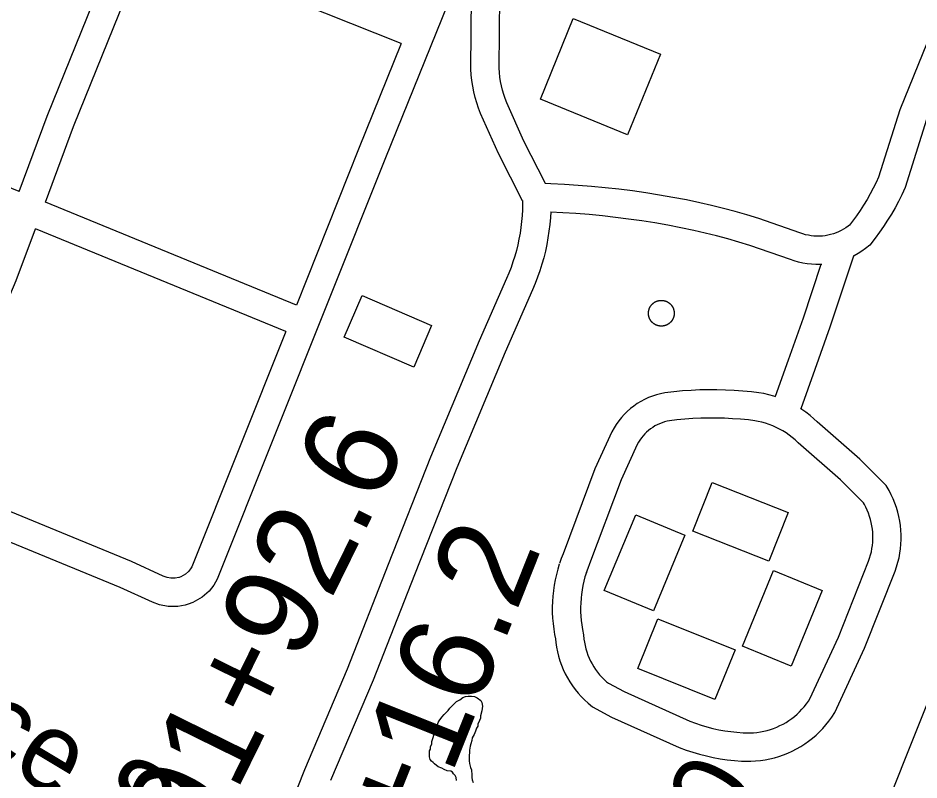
# Model space of a CAD drawing. Extents: x 3677843 to 3715951, y 511991 to 537744.
# Drawn here: x 3699179 to 3700134, y 530096 to 530904 of the extents above; entities that cross this region are included whole.
import ezdxf

# ---------------------------------------------------------------- set-up
doc = ezdxf.new("R2010")
doc.units = 0
for name, color, linetype in [('V-BLDG-IDEN', 7, 'Continuous'), ('V-BLDG-OTLN', 7, 'Continuous'), ('V-RIVR-RANG-IDEN', 7, 'Continuous'), ('V-ROAD-CNTR', 7, 'Continuous'), ('V-SITE-STRC', 7, 'Continuous'), ('V-SITE-VEGE', 7, 'Continuous'), ('V-SURV-IDEN', 7, 'Continuous'), ('V-TOPO-BNDY', 7, 'Continuous')]:
    doc.layers.add(name, color=color, linetype=linetype)

msp = doc.modelspace()

# ---------------------------------------------------------------- linework, layer by layer
at = {"layer": 'V-BLDG-OTLN'}
for points in [[(3699732.81, 530817.61), (3699767.66, 530903.08), (3699860.1, 530865.38), (3699825.24, 530779.93)], [(3699543.77, 530609.69), (3699617.52, 530578.01), (3699598.59, 530533.94), (3699524.84, 530565.62)], [(3699974.84, 530328.15), (3699894.45, 530360.14), (3699914.94, 530411.63), (3699995.33, 530379.63)], [(3699885.9, 530355.71), (3699852.63, 530275.63), (3699800.5, 530297.29), (3699833.77, 530377.36)], [(3700031.5, 530297.11), (3699998.55, 530217.03), (3699946.89, 530238.28), (3699979.83, 530318.36)], [(3699917.82, 530181.6), (3699836.15, 530214.54), (3699857.41, 530267.22), (3699939.07, 530234.27)]]:
    msp.add_lwpolyline(points, close=True, dxfattribs=at)
at = {"layer": 'V-ROAD-CNTR'}
for points in [[(3699695.42, 531069.1), (3699568.01, 530753.72), (3699390.39, 530309.01), (3699386.76, 530302.86), (3699381.67, 530296.5), (3699374.27, 530289.96), (3699364.58, 530284.44), (3699359.58, 530282.57), (3699356.41, 530281.64), (3699348.49, 530280.21), (3699338.36, 530280.19), (3699329.17, 530281.92), (3699321.57, 530284.76), (3699287.45, 530300.47), (3699085.23, 530383.37), (3699069.85, 530390.63), (3699063.87, 530399.71), (3699062.2, 530405.56), (3699060.55, 530414.61), (3699063.09, 530432.38), (3699070.46, 530451.51), (3699149.4, 530636.86), (3699169.9, 530691.83)], [(3699180.39, 530719.95), (3699210.17, 530799.78), (3699288.77, 530994.73)], [(3699208.17, 530708.58), (3699238.14, 530788.93), (3699316.64, 530983.63)], [(3699585.29, 530876.59), (3699316.64, 530983.63)], [(3700171.65, 530949.68), (3700113.85, 530806.5), (3700091.28, 530734.98), (3700088.71, 530729.46), (3700085.64, 530723.33), (3700082.39, 530717.3), (3700078.98, 530711.36), (3700075.4, 530705.51), (3700071.65, 530699.77), (3700067.74, 530694.14), (3700063.67, 530688.63), (3700060.35, 530684.39), (3700059.03, 530683.31), (3700056.61, 530681.57), (3700054.1, 530679.97), (3700051.5, 530678.51), (3700048.83, 530677.2), (3700046.08, 530676.04), (3700043.27, 530675.04), (3700040.42, 530674.21), (3700037.52, 530673.53), (3700034.58, 530673.02), (3700031.61, 530672.68), (3700028.64, 530672.51), (3700025.66, 530672.5), (3700022.69, 530672.67), (3700019.73, 530673), (3700016.79, 530673.5), (3700013.88, 530674.17), (3700011.02, 530675), (3700007.79, 530676.13), (3699964.22, 530691.33), (3699951.7, 530695.13), (3699939.29, 530698.65), (3699926.82, 530701.97), (3699914.3, 530705.07), (3699901.7, 530707.96), (3699887.47, 530710.93), (3699873.24, 530713.65), (3699858.97, 530716.16), (3699844.66, 530718.44), (3699830.31, 530720.49), (3699815.94, 530722.32), (3699801.54, 530723.92), (3699787.11, 530725.3), (3699772.66, 530726.45), (3699758.2, 530727.37), (3699743.72, 530728.07), (3699737.73, 530728.26)], [(3699713.9, 530709.9), (3699688.24, 530760.35), (3699669.38, 530802.45), (3699667.18, 530808.16), (3699665.27, 530813.89), (3699663.6, 530819.7), (3699662.2, 530825.58), (3699661.06, 530831.51), (3699660.18, 530837.5), (3699659.56, 530843.51), (3699659.21, 530849.69), (3699659.71, 530927.96)], [(3699738.22, 530728.25), (3699715.31, 530773.29), (3699697.09, 530813.98), (3699695.42, 530818.31), (3699693.93, 530822.78), (3699692.63, 530827.32), (3699691.53, 530831.9), (3699690.64, 530836.53), (3699689.95, 530841.2), (3699689.48, 530845.89), (3699689.21, 530850.45), (3699689.71, 530927.25)], [(3699585.29, 530876.59), (3699540.17, 530764.9), (3699474.16, 530599.62)], [(3699180.39, 530719.95), (3698900.65, 530834.54)], [(3700142.11, 530796.35), (3700119.3, 530724.08), (3700115.72, 530716.41), (3700112.27, 530709.51), (3700108.62, 530702.72), (3700104.78, 530696.04), (3700100.75, 530689.47), (3700096.53, 530683.01), (3700092.13, 530676.68), (3700087.56, 530670.47), (3700081.89, 530663.24), (3700077.28, 530659.49), (3700073.48, 530656.75), (3700069.53, 530654.23), (3700065.45, 530651.93), (3700064.39, 530651.41)], [(3699474.16, 530599.62), (3699208.17, 530708.58)], [(3699713.9, 530710.36), (3699713.92, 530706.93), (3699713.77, 530700.66), (3699713.43, 530694.41), (3699712.89, 530688.16), (3699712.16, 530681.93), (3699711.23, 530675.73), (3699710.12, 530669.56), (3699708.81, 530663.43), (3699707.31, 530657.34), (3699705.62, 530651.3), (3699703.75, 530645.32), (3699701.69, 530639.39), (3699699.45, 530633.54), (3699696.99, 530627.66), (3699667.95, 530561.55), (3699616.43, 530438.58), (3699571.63, 530324.75), (3699527.9, 530213.65), (3699482.69, 530107.12), (3699459.1, 530047.48)], [(3699743.69, 530698.3), (3699743.36, 530692.3), (3699742.74, 530685.12), (3699741.9, 530677.97), (3699740.84, 530670.84), (3699739.55, 530663.76), (3699738.05, 530656.72), (3699736.33, 530649.72), (3699734.39, 530642.78), (3699732.24, 530635.91), (3699729.87, 530629.1), (3699727.3, 530622.38), (3699724.56, 530615.83), (3699695.52, 530549.72), (3699644.22, 530427.29), (3699599.54, 530313.77), (3699555.67, 530202.29), (3699510.45, 530095.75)], [(3700031.03, 530642.6), (3700029.54, 530642.51), (3700024.86, 530642.5), (3700020.18, 530642.76), (3700015.53, 530643.28), (3700010.91, 530644.07), (3700006.36, 530645.11), (3700001.86, 530646.41), (3699997.86, 530647.82), (3699954.93, 530662.8), (3699943.25, 530666.34), (3699931.33, 530669.73), (3699919.36, 530672.91), (3699907.34, 530675.89), (3699895.29, 530678.66), (3699881.6, 530681.51), (3699867.83, 530684.14), (3699854.02, 530686.57), (3699840.17, 530688.77), (3699826.29, 530690.76), (3699812.38, 530692.53), (3699798.45, 530694.08), (3699784.49, 530695.42), (3699770.52, 530696.53), (3699756.52, 530697.42), (3699743.43, 530698.05)], [(3699463.03, 530571.76), (3699363.39, 530322.28), (3699362.01, 530319.95), (3699359.87, 530317.27), (3699356.72, 530314.49), (3699351.81, 530311.69), (3699350.11, 530311.06), (3699349.52, 530310.88), (3699345.77, 530310.2), (3699341.13, 530310.2), (3699337.25, 530310.92), (3699333.12, 530312.47), (3699299.42, 530327.99), (3699097.33, 530410.84), (3699090.28, 530414.16), (3699091.45, 530412.37), (3699091.45, 530412.4), (3699090.94, 530415.2), (3699092.3, 530424.76), (3699098.26, 530440.24), (3699177.27, 530625.73), (3699197.68, 530680.45)], [(3699463.03, 530571.76), (3699197.68, 530680.45)], [(3700064.74, 530651.58), (3700039.71, 530576.02), (3700023.62, 530531.23), (3700008.77, 530489.74)], [(3700030.14, 530642.54), (3700011.35, 530585.81), (3699995.38, 530541.35), (3699981.53, 530502.66)], [(3699982.21, 530502.44), (3699980.3, 530503.07), (3699975.05, 530504.55), (3699969.73, 530505.77), (3699964.27, 530506.74), (3699956.42, 530507.66), (3699947.32, 530508.51), (3699938.21, 530509.15), (3699929.09, 530509.58), (3699919.95, 530509.8), (3699910.81, 530509.81), (3699901.67, 530509.61), (3699892.54, 530509.2), (3699883.42, 530508.57), (3699874.32, 530507.74), (3699864.77, 530506.64), (3699860.16, 530505.71), (3699855.82, 530504.56), (3699851.55, 530503.16), (3699847.36, 530501.51), (3699843.28, 530499.63), (3699839.32, 530497.52), (3699835.49, 530495.18), (3699831.79, 530492.62), (3699828.26, 530489.85), (3699824.88, 530486.88), (3699821.68, 530483.72), (3699818.68, 530480.39), (3699815.87, 530476.89), (3699813.26, 530473.22), (3699810.88, 530469.41), (3699808.66, 530465.37), (3699790.66, 530426), (3699756.82, 530336), (3699754.84, 530330.94), (3699753.01, 530325.7)], [(3699746.52, 530296.73), (3699745.94, 530291.21), (3699745.55, 530285.4), (3699745.38, 530279.57), (3699745.43, 530273.74), (3699745.71, 530267.91), (3699746.21, 530262.1), (3699746.94, 530256.31), (3699747.88, 530250.56), (3699748.83, 530245.9), (3699749.2, 530242.11), (3699749.91, 530237.2), (3699750.87, 530232.34), (3699752.06, 530227.52), (3699753.49, 530222.77), (3699755.14, 530218.1), (3699757.03, 530213.5), (3699759.14, 530209.02), (3699761.46, 530204.64), (3699764, 530200.37), (3699766.74, 530196.24), (3699769.68, 530192.24), (3699772.81, 530188.4), (3699776.13, 530184.71), (3699779.63, 530181.19), (3699783.29, 530177.84), (3699787.96, 530173.97), (3699808.24, 530163.05), (3699879.84, 530130.82), (3699887.13, 530128.13), (3699894.26, 530125.79), (3699901.46, 530123.69), (3699908.73, 530121.84), (3699916.07, 530120.24), (3699923.45, 530118.91), (3699930.88, 530117.82), (3699938.34, 530117), (3699945.8, 530116.44), (3699950.74, 530116.23), (3699955.8, 530116.25), (3699960.86, 530116.5), (3699965.91, 530117), (3699970.91, 530117.73), (3699975.88, 530118.69), (3699980.81, 530119.89), (3699985.67, 530121.32), (3699990.46, 530122.98), (3699995.16, 530124.86), (3699999.77, 530126.96), (3700004.28, 530129.27), (3700008.67, 530131.8), (3700012.94, 530134.52), (3700017.08, 530137.45), (3700021.07, 530140.57), (3700024.91, 530143.87), (3700028.59, 530147.35), (3700032.11, 530151), (3700035.45, 530154.81), (3700038.6, 530158.77), (3700041.56, 530162.88), (3700044.74, 530167.74), (3700076.2, 530235.95), (3700108.75, 530317.71), (3700110.35, 530322.33), (3700111.72, 530327.03), (3700112.88, 530331.79), (3700113.8, 530336.61), (3700114.49, 530341.46), (3700114.94, 530346.34), (3700115.16, 530351.24), (3700115.15, 530356.14), (3700114.9, 530361.03), (3700114.42, 530365.91), (3700113.7, 530370.75), (3700112.75, 530375.57), (3700111.57, 530380.33), (3700110.17, 530385.02), (3700108.54, 530389.64), (3700106.69, 530394.18), (3700104.63, 530398.63), (3700102.35, 530402.96), (3700099.09, 530408.53), (3700071.3, 530436.34), (3700026.19, 530475.78), (3700022.69, 530479.08), (3700018.55, 530482.63), (3700014.24, 530485.97), (3700009.78, 530489.1), (3700008.62, 530489.83)], [(3699776.35, 530293.58), (3699775.83, 530288.63), (3699775.52, 530283.96), (3699775.38, 530279.28), (3699775.42, 530274.6), (3699775.65, 530269.92), (3699776.05, 530265.26), (3699776.63, 530260.61), (3699777.39, 530255.99), (3699778.54, 530250.34), (3699778.99, 530245.72), (3699779.49, 530242.27), (3699780.17, 530238.83), (3699781, 530235.45), (3699782.01, 530232.11), (3699783.17, 530228.81), (3699784.5, 530225.59), (3699785.99, 530222.42), (3699787.62, 530219.34), (3699789.4, 530216.34), (3699791.33, 530213.43), (3699793.4, 530210.62), (3699795.61, 530207.91), (3699797.94, 530205.32), (3699800.4, 530202.84), (3699802.98, 530200.48), (3699804.81, 530198.97), (3699821.52, 530189.97), (3699891.2, 530158.61), (3699897.02, 530156.46), (3699903.15, 530154.44), (3699909.36, 530152.63), (3699915.62, 530151.04), (3699921.93, 530149.67), (3699928.29, 530148.52), (3699934.68, 530147.59), (3699941.1, 530146.88), (3699947.57, 530146.4), (3699951.34, 530146.23), (3699955, 530146.24), (3699958.64, 530146.43), (3699962.27, 530146.78), (3699965.89, 530147.31), (3699969.48, 530148.01), (3699973.02, 530148.87), (3699976.53, 530149.9), (3699979.98, 530151.1), (3699983.37, 530152.45), (3699986.7, 530153.96), (3699989.95, 530155.63), (3699993.11, 530157.45), (3699996.19, 530159.42), (3699999.17, 530161.53), (3700002.05, 530163.78), (3700004.82, 530166.16), (3700007.48, 530168.67), (3700010.01, 530171.3), (3700012.41, 530174.04), (3700014.69, 530176.9), (3700016.82, 530179.86), (3700018.41, 530182.3), (3700048.63, 530247.79), (3700080.62, 530328.18), (3700081.76, 530331.46), (3700082.73, 530334.78), (3700083.55, 530338.15), (3700084.2, 530341.54), (3700084.68, 530344.97), (3700085.01, 530348.42), (3700085.16, 530351.88), (3700085.15, 530355.34), (3700084.98, 530358.79), (3700084.64, 530362.24), (3700084.13, 530365.66), (3700083.46, 530369.05), (3700082.63, 530372.41), (3700081.63, 530375.73), (3700080.49, 530378.99), (3700079.18, 530382.2), (3700077.72, 530385.33), (3700076.12, 530388.4), (3700075.15, 530390.04), (3700050.79, 530414.42), (3700006.01, 530453.57), (3700002.63, 530456.76), (3699999.59, 530459.37), (3699996.42, 530461.83), (3699993.14, 530464.13), (3699989.76, 530466.27), (3699986.27, 530468.24), (3699982.69, 530470.04), (3699979.03, 530471.67), (3699975.29, 530473.12), (3699971.49, 530474.39), (3699967.64, 530475.47), (3699963.74, 530476.36), (3699959.89, 530477.05), (3699953.28, 530477.82), (3699944.87, 530478.61), (3699936.45, 530479.2), (3699928.01, 530479.6), (3699919.57, 530479.81), (3699911.13, 530479.81), (3699902.68, 530479.63), (3699894.24, 530479.24), (3699885.81, 530478.67), (3699877.4, 530477.9), (3699869.49, 530476.99), (3699867, 530476.48), (3699864.33, 530475.78), (3699861.71, 530474.92), (3699859.14, 530473.91), (3699856.64, 530472.76), (3699854.21, 530471.46), (3699851.86, 530470.02), (3699849.59, 530468.45), (3699847.42, 530466.75), (3699845.35, 530464.93), (3699843.39, 530463), (3699841.54, 530460.94), (3699839.82, 530458.8), (3699838.22, 530456.55), (3699836.76, 530454.21), (3699835.49, 530451.9), (3699818.38, 530414.47), (3699784.83, 530325.25), (3699782.97, 530320.52), (3699781.34, 530315.83)], [(3699752.83, 530325.15), (3699751.21, 530319.85), (3699749.72, 530314.22), (3699748.44, 530308.53), (3699747.39, 530302.79), (3699746.59, 530297.31)], [(3699781.52, 530316.38), (3699780.06, 530311.62), (3699778.87, 530307.1), (3699777.84, 530302.53), (3699776.99, 530297.92), (3699776.28, 530293)]]:
    msp.add_lwpolyline(points, dxfattribs=at)
at = {"layer": 'V-SITE-STRC'}
for points in [[(3699848.12, 530595.59), (3699848.21, 530595.81), (3699848.29, 530596.03), (3699848.39, 530596.25), (3699848.48, 530596.47), (3699848.58, 530596.69), (3699848.68, 530596.9), (3699848.79, 530597.12), (3699848.9, 530597.33), (3699849.01, 530597.54), (3699849.12, 530597.74), (3699849.25, 530597.95), (3699849.37, 530598.15), (3699849.5, 530598.35), (3699849.63, 530598.55), (3699849.77, 530598.75), (3699849.9, 530598.94), (3699850.04, 530599.13), (3699850.19, 530599.32), (3699850.34, 530599.51), (3699850.49, 530599.7), (3699850.65, 530599.88), (3699850.8, 530600.05), (3699850.96, 530600.23), (3699851.13, 530600.4), (3699851.29, 530600.57), (3699851.46, 530600.74), (3699851.64, 530600.9), (3699851.81, 530601.07), (3699851.99, 530601.22), (3699852.17, 530601.38), (3699852.35, 530601.53), (3699852.54, 530601.68), (3699852.73, 530601.82), (3699852.92, 530601.97), (3699853.12, 530602.1), (3699853.31, 530602.24), (3699853.51, 530602.37), (3699853.71, 530602.5), (3699853.91, 530602.62), (3699854.12, 530602.74), (3699854.33, 530602.86), (3699854.53, 530602.98), (3699854.75, 530603.09), (3699854.96, 530603.19), (3699855.17, 530603.3), (3699855.39, 530603.4), (3699855.61, 530603.49), (3699855.83, 530603.58), (3699856.05, 530603.67), (3699856.27, 530603.75), (3699856.5, 530603.83), (3699856.72, 530603.91), (3699856.95, 530603.98), (3699857.18, 530604.05), (3699857.41, 530604.11), (3699857.64, 530604.17), (3699857.87, 530604.23), (3699858.1, 530604.28), (3699858.33, 530604.33), (3699858.57, 530604.37)], [(3699858.57, 530604.37), (3699858.8, 530604.41), (3699859.04, 530604.45), (3699859.28, 530604.48), (3699859.51, 530604.5), (3699859.75, 530604.53), (3699859.99, 530604.55), (3699860.23, 530604.56), (3699860.46, 530604.57), (3699860.7, 530604.58), (3699860.94, 530604.58), (3699861.18, 530604.58), (3699861.42, 530604.57), (3699861.66, 530604.56), (3699861.89, 530604.55), (3699862.13, 530604.53), (3699862.37, 530604.51), (3699862.6, 530604.48), (3699862.84, 530604.45), (3699863.07, 530604.42), (3699863.31, 530604.38), (3699863.54, 530604.33), (3699863.78, 530604.29), (3699864.01, 530604.24), (3699864.24, 530604.18), (3699864.47, 530604.12), (3699864.7, 530604.06), (3699864.93, 530603.99), (3699865.16, 530603.92), (3699865.38, 530603.84), (3699865.61, 530603.76), (3699865.83, 530603.68), (3699866.05, 530603.59), (3699866.27, 530603.5), (3699866.49, 530603.41), (3699866.71, 530603.31), (3699866.92, 530603.21), (3699867.14, 530603.1), (3699867.35, 530602.99), (3699867.56, 530602.88), (3699867.77, 530602.76), (3699867.97, 530602.64), (3699868.17, 530602.52), (3699868.38, 530602.39), (3699868.58, 530602.26), (3699868.77, 530602.12), (3699868.96, 530601.98), (3699869.16, 530601.84), (3699869.34, 530601.7), (3699869.53, 530601.55), (3699869.72, 530601.4), (3699869.9, 530601.24), (3699870.08, 530601.09), (3699870.25, 530600.92), (3699870.42, 530600.76), (3699870.59, 530600.59), (3699870.76, 530600.42), (3699870.92, 530600.25), (3699871.09, 530600.08), (3699871.25, 530599.9), (3699871.4, 530599.72), (3699871.55, 530599.53), (3699871.7, 530599.35), (3699871.85, 530599.16), (3699871.99, 530598.97), (3699872.13, 530598.77), (3699872.26, 530598.58), (3699872.39, 530598.38), (3699872.52, 530598.18), (3699872.65, 530597.97), (3699872.77, 530597.77), (3699872.88, 530597.56), (3699873, 530597.35), (3699873.11, 530597.14), (3699873.22, 530596.93), (3699873.32, 530596.71), (3699873.42, 530596.5), (3699873.51, 530596.28), (3699873.6, 530596.06), (3699873.69, 530595.84), (3699873.77, 530595.62), (3699873.85, 530595.39), (3699873.93, 530595.17), (3699874, 530594.94), (3699874.07, 530594.71), (3699874.13, 530594.48), (3699874.2, 530594.25), (3699874.25, 530594.02), (3699874.3, 530593.79), (3699874.35, 530593.55), (3699874.39, 530593.32), (3699874.43, 530593.08), (3699874.47, 530592.85), (3699874.5, 530592.61), (3699874.53, 530592.37), (3699874.55, 530592.14), (3699874.57, 530591.9), (3699874.58, 530591.66), (3699874.59, 530591.42), (3699874.6, 530591.19), (3699874.6, 530590.95)], [(3699858.6, 530577.49), (3699858.36, 530577.53), (3699858.13, 530577.58), (3699857.9, 530577.63), (3699857.67, 530577.69), (3699857.44, 530577.74), (3699857.21, 530577.81), (3699856.98, 530577.88), (3699856.75, 530577.95), (3699856.52, 530578.02), (3699856.3, 530578.1), (3699856.08, 530578.19), (3699855.85, 530578.27), (3699855.64, 530578.36), (3699855.42, 530578.46), (3699855.2, 530578.56), (3699854.98, 530578.66), (3699854.77, 530578.77), (3699854.56, 530578.88), (3699854.35, 530578.99), (3699854.14, 530579.1), (3699853.94, 530579.23), (3699853.73, 530579.35), (3699853.53, 530579.48), (3699853.33, 530579.61), (3699853.14, 530579.74), (3699852.95, 530579.88), (3699852.75, 530580.02), (3699852.56, 530580.17), (3699852.38, 530580.32), (3699852.19, 530580.47), (3699852.01, 530580.62), (3699851.83, 530580.78), (3699851.66, 530580.94), (3699851.48, 530581.11), (3699851.31, 530581.27), (3699851.15, 530581.44), (3699850.98, 530581.61), (3699850.82, 530581.79), (3699850.66, 530581.97), (3699850.51, 530582.15), (3699850.36, 530582.33), (3699850.21, 530582.52), (3699850.06, 530582.71), (3699849.92, 530582.9), (3699849.78, 530583.09), (3699849.65, 530583.29), (3699849.52, 530583.49), (3699849.39, 530583.69), (3699849.26, 530583.89), (3699849.14, 530584.1), (3699849.02, 530584.3), (3699848.91, 530584.51), (3699848.8, 530584.72), (3699848.69, 530584.94), (3699848.59, 530585.15), (3699848.49, 530585.37), (3699848.4, 530585.59), (3699848.31, 530585.81), (3699848.22, 530586.03), (3699848.13, 530586.25), (3699848.05, 530586.47), (3699847.98, 530586.7), (3699847.91, 530586.93), (3699847.84, 530587.16), (3699847.78, 530587.39), (3699847.71, 530587.62), (3699847.66, 530587.85), (3699847.61, 530588.08), (3699847.56, 530588.32), (3699847.52, 530588.55), (3699847.48, 530588.78), (3699847.44, 530589.02), (3699847.41, 530589.26), (3699847.38, 530589.49), (3699847.36, 530589.73), (3699847.34, 530589.96), (3699847.33, 530590.2), (3699847.31, 530590.44), (3699847.31, 530590.68), (3699847.31, 530590.92), (3699847.31, 530591.16), (3699847.31, 530591.4), (3699847.32, 530591.63), (3699847.33, 530591.87), (3699847.36, 530592.11), (3699847.38, 530592.34), (3699847.41, 530592.58), (3699847.44, 530592.82), (3699847.47, 530593.05), (3699847.51, 530593.29), (3699847.55, 530593.52), (3699847.6, 530593.76), (3699847.65, 530593.99), (3699847.71, 530594.22), (3699847.77, 530594.45), (3699847.83, 530594.68), (3699847.9, 530594.91), (3699847.97, 530595.14), (3699848.04, 530595.36), (3699848.12, 530595.59)], [(3699874.6, 530590.95), (3699874.6, 530590.71), (3699874.59, 530590.47), (3699874.58, 530590.23), (3699874.57, 530590), (3699874.55, 530589.76), (3699874.53, 530589.52), (3699874.5, 530589.28), (3699874.47, 530589.05), (3699874.44, 530588.81), (3699874.4, 530588.58), (3699874.36, 530588.34), (3699874.31, 530588.11), (3699874.26, 530587.88), (3699874.2, 530587.65), (3699874.14, 530587.42), (3699874.08, 530587.18), (3699874.01, 530586.96), (3699873.94, 530586.73), (3699873.87, 530586.5), (3699873.79, 530586.28), (3699873.7, 530586.06), (3699873.62, 530585.83), (3699873.52, 530585.61), (3699873.43, 530585.4), (3699873.33, 530585.18), (3699873.23, 530584.96), (3699873.12, 530584.75), (3699873.01, 530584.54), (3699872.9, 530584.33), (3699872.78, 530584.12), (3699872.66, 530583.92), (3699872.53, 530583.71), (3699872.41, 530583.51), (3699872.28, 530583.31), (3699872.14, 530583.12), (3699872.01, 530582.92), (3699871.86, 530582.73), (3699871.72, 530582.54), (3699871.57, 530582.35), (3699871.42, 530582.17), (3699871.26, 530581.99), (3699871.11, 530581.81), (3699870.95, 530581.64), (3699870.78, 530581.46), (3699870.62, 530581.29), (3699870.45, 530581.13), (3699870.27, 530580.96), (3699870.1, 530580.8), (3699869.92, 530580.64), (3699869.74, 530580.49), (3699869.56, 530580.34), (3699869.37, 530580.19), (3699869.18, 530580.04), (3699868.99, 530579.9), (3699868.79, 530579.76), (3699868.6, 530579.63), (3699868.4, 530579.49), (3699868.2, 530579.37), (3699868, 530579.24), (3699867.79, 530579.12), (3699867.58, 530579), (3699867.38, 530578.89), (3699867.16, 530578.78), (3699866.95, 530578.67), (3699866.74, 530578.57), (3699866.52, 530578.47), (3699866.3, 530578.38), (3699866.08, 530578.28), (3699865.86, 530578.2), (3699865.64, 530578.11), (3699865.41, 530578.03), (3699865.19, 530577.96), (3699864.96, 530577.89), (3699864.73, 530577.82), (3699864.5, 530577.75), (3699864.27, 530577.69), (3699864.04, 530577.64), (3699863.81, 530577.58), (3699863.57, 530577.54), (3699863.34, 530577.49), (3699863.1, 530577.45), (3699862.87, 530577.42), (3699862.63, 530577.39), (3699862.4, 530577.36), (3699862.16, 530577.34), (3699861.92, 530577.32), (3699861.68, 530577.31), (3699861.45, 530577.29), (3699861.21, 530577.29), (3699860.97, 530577.28), (3699860.73, 530577.29), (3699860.49, 530577.29), (3699860.25, 530577.3), (3699860.02, 530577.32), (3699859.78, 530577.33), (3699859.54, 530577.36), (3699859.31, 530577.38), (3699859.07, 530577.42), (3699858.83, 530577.45), (3699858.6, 530577.49)]]:
    msp.add_lwpolyline(points, dxfattribs=at)
at = {"layer": 'V-SITE-VEGE'}
for points in [[(3699643.98, 530095.73), (3699643.51, 530099.06), (3699642.56, 530100.96), (3699640.65, 530102.87), (3699639.7, 530104.77), (3699637.8, 530105.73), (3699633.99, 530106.2), (3699630.66, 530107.63), (3699628.28, 530109.06), (3699624.47, 530110.49), (3699620.67, 530113.34), (3699619.24, 530114.77), (3699617.34, 530116.2), (3699615.91, 530118.1), (3699615.43, 530120.96), (3699615.44, 530127.15), (3699616.39, 530129.05), (3699616.39, 530131.43), (3699617.82, 530134.76), (3699617.82, 530137.14), (3699619.25, 530141.42), (3699619.73, 530143.8), (3699621.15, 530147.13), (3699622.11, 530151.42), (3699623.06, 530153.32), (3699624.49, 530157.13), (3699625.44, 530159.03), (3699628.3, 530162.84), (3699630.68, 530165.69), (3699634.96, 530169.97), (3699636.86, 530172.35), (3699644.01, 530179.49), (3699647.34, 530181.39), (3699650.67, 530183.77), (3699653.53, 530184.72), (3699656.38, 530185.19), (3699659.71, 530185.19), (3699663.04, 530184.72), (3699665.9, 530183.29), (3699669.7, 530180.43), (3699670.66, 530178.53), (3699671.61, 530174.72), (3699670.65, 530169.49), (3699669.23, 530164.25), (3699669.23, 530161.87), (3699668.27, 530159.49), (3699666.37, 530155.69), (3699666.37, 530153.31), (3699664.94, 530151.41)], [(3699664.94, 530151.41), (3699663.98, 530148.07), (3699662.56, 530144.74), (3699660.65, 530140.94), (3699660.18, 530138.08), (3699659.22, 530134.75), (3699658.27, 530132.37), (3699657.79, 530128.09), (3699657.79, 530125.71), (3699657.31, 530121.9), (3699657.31, 530116.66), (3699657.79, 530113.81), (3699658.74, 530109.53), (3699659.69, 530107.15), (3699660.17, 530101.44), (3699660.16, 530099.06), (3699660.64, 530096.68), (3699661.59, 530093.82)]]:
    msp.add_lwpolyline(points, dxfattribs=at)
at = {"layer": 'V-TOPO-BNDY'}
msp.add_line((3699901.51, 529570.14), (3702384.98, 535822.49), dxfattribs=at)

# ---------------------------------------------------------------- texts
at = {"layer": 'V-BLDG-IDEN'}
msp.add_text('St. Maurice St. Wharf', height=82.9998, rotation=329.11883, dxfattribs=at).set_placement((3698741.31, 530362.65))
at = {"layer": 'V-RIVR-RANG-IDEN'}
msp.add_text('D-030', height=83, rotation=60.51933, dxfattribs=at).set_placement((3699816.69, 529826.59))
at = {"layer": 'V-SURV-IDEN'}
for s, rotation, p in [('   691+92.6   ', 63.80671, (3699295.53, 529849.15)), ('   694+16.2   ', 68.31235, (3699485.79, 529717.17))]:
    msp.add_text(s, height=100, rotation=rotation, dxfattribs=at).set_placement(p)

doc.saveas('drawing.dxf')
